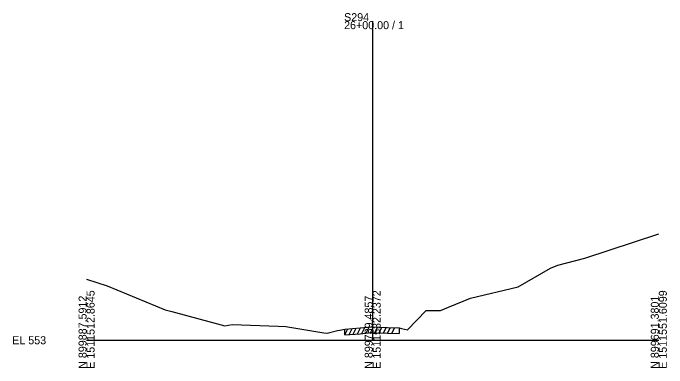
# Model space of a CAD drawing. Extents: x 974 to 2203, y -10 to 19041.
# Drawn here: x 1974.3 to 2202.8, y 11990.3 to 12114.5 of the extents above; entities that cross this region are included whole.
import ezdxf

# ---------------------------------------------------------------- set-up
doc = ezdxf.new("R2010")
doc.units = 0
for name, color, linetype in [('RD_GPK_XS_Cell', 7, 'Continuous'), ('RD_XS_ExGround', 7, 'Continuous'), ('RD_XS_ExPaveRet', 7, 'Continuous'), ('RD_XS_TX_Elev_EX', 7, 'Continuous')]:
    doc.layers.add(name, color=color, linetype=linetype)

msp = doc.modelspace()

# ---------------------------------------------------------------- linework, layer by layer
at = {"layer": 'RD_GPK_XS_Cell'}
for p, q in [((2100, 12000), (2100, 12111.7)), ((2000, 12000), (2100, 12000)), ((2100, 12000), (2200, 12000))]:
    msp.add_line(p, q, dxfattribs=at)
at = {"layer": 'RD_XS_ExGround'}
msp.add_lwpolyline([(2000, 12021.44), (2007.17, 12019.04), (2027.47, 12010.69), (2029.81, 12010.05), (2048.27, 12005.04), (2050.87, 12005.51), (2067.01, 12004.88), (2069.64, 12004.8), (2082.9, 12002.65), (2084.12, 12002.46), (2087.73, 12003.39), (2088.53, 12003.55), (2090.23, 12003.91), (2095.59, 12004.3), (2099.53, 12004.67), (2100, 12004.65), (2105.2, 12004.45), (2109.21, 12004.39), (2110.07, 12004.09), (2112.22, 12003.63), (2118.64, 12010.45), (2123.69, 12010.4), (2126.5, 12011.56), (2134.22, 12014.75), (2150.86, 12018.74), (2162.1, 12025.22), (2164.75, 12026.3), (2174.15, 12028.79), (2200, 12037.23)], dxfattribs=at)
at = {"layer": 'RD_XS_ExPaveRet'}
for p, q in [((2090.23, 12001.91), (2091.27, 12003.99)), ((2090.23, 12001.91), (2090.23, 12003.91)), ((2091.73, 12002.02), (2092.77, 12004.1)), ((2093.23, 12002.13), (2094.27, 12004.21)), ((2094.73, 12002.24), (2095.77, 12004.32)), ((2095.59, 12002.3), (2099.53, 12002.67)), ((2096.23, 12002.36), (2097.28, 12004.46)), ((2097.73, 12002.5), (2098.78, 12004.6)), ((2099.23, 12002.64), (2100.23, 12004.64)), ((2099.53, 12002.67), (2100, 12002.65)), ((2100, 12002.65), (2105.2, 12002.45)), ((2100.73, 12002.62), (2101.71, 12004.59)), ((2102.23, 12002.57), (2103.21, 12004.53)), ((2103.73, 12002.51), (2104.71, 12004.47)), ((2105.23, 12002.45), (2106.22, 12004.44)), ((2106.73, 12002.43), (2107.72, 12004.41)), ((2109.21, 12004.39), (2109.21, 12002.39)), ((2090.23, 12001.91), (2095.59, 12002.3)), ((2105.2, 12002.45), (2109.21, 12002.39))]:
    msp.add_line(p, q, dxfattribs=at)

# ---------------------------------------------------------------- texts
at = {"layer": 'RD_GPK_XS_Cell'}
for s, p in [('S294', (2090, 12111.7)), ('26+00.00 / 1', (2090, 12108.9)), ('EL 553', (1974, 11998.6))]:
    msp.add_text(s, height=2.8, dxfattribs=at).set_placement(p)
for s, p in [('E 1511512.8645', (2002.8, 11990)), ('E 1511532.2372', (2102.8, 11990)), ('E 1511551.6099', (2202.8, 11990)), ('N 899887.5912', (2000, 11990)), ('N 899789.4857', (2100, 11990)), ('N 899691.3801', (2200, 11990))]:
    msp.add_text(s, height=2.8, rotation=90, dxfattribs=at).set_placement(p)
at = {"layer": 'RD_XS_TX_Elev_EX'}
msp.add_text('555.33', height=0.75, rotation=90, dxfattribs=at).set_placement((2100, 12004.65))

doc.saveas('drawing.dxf')
